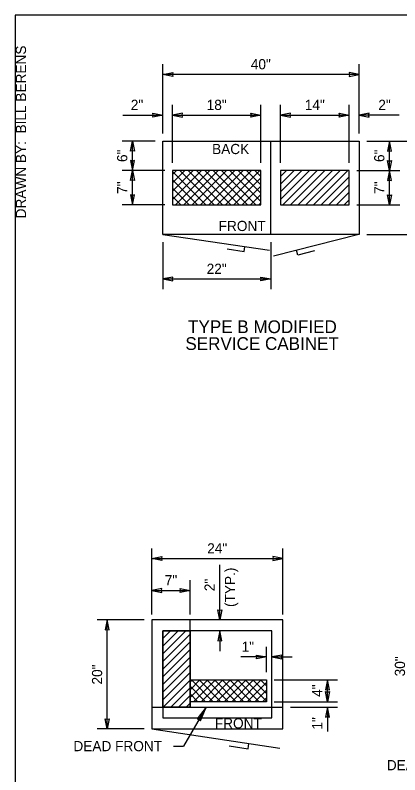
# Model space of a CAD drawing. Extents: x 99862 to 103151, y 100000 to 117076.
# Drawn here: x 99862 to 100465, y 100884 to 102076 of the extents above; entities that cross this region are included whole.
import ezdxf

# ---------------------------------------------------------------- set-up
doc = ezdxf.new("R2010")
doc.units = 0
for name, color, linetype in [('Level 1', 7, 'Continuous'), ('Level 15', 7, 'Continuous'), ('Level 20', 7, 'Continuous'), ('Level 25', 7, 'Continuous'), ('Level 40', 7, 'Continuous'), ('Level 62', 7, 'Continuous'), ('Level 8', 7, 'Continuous')]:
    doc.layers.add(name, color=color, linetype=linetype)

msp = doc.modelspace()

# ---------------------------------------------------------------- linework, layer by layer
at = {"layer": 'Level 1'}
msp.add_lwpolyline([(99862, 99999.5), (103151, 99999.5), (103151, 102075.5), (99862, 102075.5)], close=True, dxfattribs=at)
at = {"layer": 'Level 15'}
for p, q in [((100093.5, 101889.9), (100093.5, 101998.6)), ((100401.3, 101889.9), (100401.3, 101998.6)), ((100401.3, 101982.6), (100093.5, 101982.6)), ((100093.5, 101889.9), (100093.5, 101934.8)), ((100108.9, 101843.7), (100108.9, 101934.8)), ((100247.4, 101843.7), (100247.4, 101934.8)), ((100278.2, 101843.7), (100278.2, 101934.8)), ((100385.9, 101843.7), (100385.9, 101934.8)), ((100401.3, 101889.9), (100401.3, 101934.8)), ((100030.6, 101918.8), (100093.5, 101918.8)), ((100108.9, 101918.8), (100247.4, 101918.8)), ((100278.2, 101918.8), (100385.9, 101918.8)), ((100464.2, 101918.8), (100401.3, 101918.8)), ((100081.5, 101877.9), (100029.8, 101877.9)), ((100045.8, 101831.7), (100045.8, 101877.9)), ((100413.3, 101877.9), (100515, 101877.9)), ((100449, 101831.7), (100449, 101877.9)), ((100096.9, 101831.7), (100029.8, 101831.7)), ((100045.8, 101777.9), (100045.8, 101831.7)), ((100397.9, 101831.7), (100465, 101831.7)), ((100449, 101777.9), (100449, 101831.7)), ((100096.9, 101777.9), (100029.8, 101777.9)), ((100397.9, 101777.9), (100465, 101777.9)), ((100413.3, 101731.7), (100515, 101731.7)), ((100093.5, 101719.7), (100093.5, 101645.7)), ((100262.8, 101719.7), (100262.8, 101645.7)), ((100093.5, 101661.7), (100262.8, 101661.7)), ((100076.4, 101149.9), (100076.4, 101239.2)), ((100281.6, 101135.2), (100281.6, 101239.2)), ((100076.4, 101223.2), (100281.6, 101223.2)), ((100076.4, 101135.2), (100076.4, 101213)), ((100182.9, 101127), (100182.9, 101213.6)), ((100136.2, 101135.2), (100136.2, 101189.2)), ((100076.4, 101173.2), (100136.2, 101173.2)), ((100064.4, 101127), (99990.4, 101127)), ((100006.4, 100956), (100006.4, 101127)), ((100182.9, 101109.9), (100182.9, 101077.9)), ((100255.9, 101044.9), (100255.9, 101084.9)), ((100255.9, 101068.9), (100215.8, 101068.9)), ((100264.5, 101068.9), (100296.5, 101068.9)), ((100267.9, 101032.9), (100367.7, 101032.9)), ((100351.7, 100998.7), (100351.7, 101032.9)), ((100267.9, 100998.7), (100367.7, 100998.7)), ((100161.5, 100990.2), (100126.2, 100929)), ((100293.7, 100990.2), (100367.7, 100990.2)), ((100351.7, 100990.2), (100351.7, 100951.8)), ((100064.4, 100956), (99990.4, 100956)), ((100110.2, 100929), (100126.2, 100929))]:
    msp.add_line(p, q, dxfattribs=at)
for points in [[(100093.5, 101982.6), (100109.2, 101985.7), (100108.5, 101982.6), (100109.2, 101979.5)], [(100401.3, 101982.6), (100385.6, 101985.7), (100386.3, 101982.6), (100385.6, 101979.5)], [(100093.5, 101918.8), (100077.8, 101915.8), (100078.5, 101918.8), (100077.8, 101921.9)], [(100108.9, 101918.8), (100124.6, 101915.8), (100123.9, 101918.8), (100124.6, 101921.9)], [(100247.4, 101918.8), (100231.7, 101915.8), (100232.4, 101918.8), (100231.7, 101921.9)], [(100278.2, 101918.8), (100293.9, 101915.8), (100293.2, 101918.8), (100293.9, 101921.9)], [(100385.9, 101918.8), (100370.2, 101915.8), (100370.9, 101918.8), (100370.2, 101921.9)], [(100401.3, 101918.8), (100417, 101915.8), (100416.3, 101918.8), (100417, 101921.9)], [(100045.8, 101877.9), (100048.9, 101862.2), (100045.8, 101862.9), (100042.7, 101862.2)], [(100449, 101877.9), (100445.9, 101862.2), (100449, 101862.9), (100452.1, 101862.2)], [(100045.8, 101831.7), (100048.9, 101847.5), (100045.8, 101846.7), (100042.7, 101847.5)], [(100449, 101831.7), (100445.9, 101847.5), (100449, 101846.7), (100452.1, 101847.5)], [(100045.8, 101831.7), (100048.9, 101816), (100045.8, 101816.7), (100042.7, 101816)], [(100449, 101831.7), (100445.9, 101816), (100449, 101816.7), (100452.1, 101816)], [(100045.8, 101777.9), (100048.9, 101793.6), (100045.8, 101792.9), (100042.7, 101793.6)], [(100449, 101777.9), (100445.9, 101793.6), (100449, 101792.9), (100452.1, 101793.6)], [(100093.5, 101661.7), (100109.2, 101658.6), (100108.5, 101661.7), (100109.2, 101664.8)], [(100262.8, 101661.7), (100247.1, 101658.6), (100247.8, 101661.7), (100247.1, 101664.8)], [(100076.4, 101223.2), (100092.1, 101226.3), (100091.4, 101223.2), (100092.1, 101220.2)], [(100281.6, 101223.2), (100265.9, 101226.3), (100266.6, 101223.2), (100265.9, 101220.2)], [(100076.4, 101173.2), (100092.1, 101170.2), (100091.4, 101173.2), (100092.1, 101176.3)], [(100136.2, 101173.2), (100120.5, 101170.2), (100121.2, 101173.2), (100120.5, 101176.3)], [(100182.9, 101127), (100179.9, 101142.7), (100182.9, 101142), (100186, 101142.7)], [(100006.4, 101127), (100003.3, 101111.3), (100006.4, 101112), (100009.5, 101111.3)], [(100182.9, 101109.9), (100179.9, 101094.2), (100182.9, 101094.9), (100186, 101094.2)], [(100255.9, 101068.9), (100240.2, 101065.8), (100240.9, 101068.9), (100240.2, 101071.9)], [(100264.5, 101068.9), (100280.2, 101065.8), (100279.5, 101068.9), (100280.2, 101071.9)], [(100351.7, 101032.9), (100348.6, 101017.2), (100351.7, 101017.9), (100354.8, 101017.2)], [(100351.7, 100998.7), (100348.6, 101014.5), (100351.7, 101013.7), (100354.8, 101014.5)], [(100161.5, 100990.2), (100147.5, 100971.9), (100150.6, 100971.3), (100152.6, 100968.9)], [(100351.7, 100990.2), (100348.6, 100974.5), (100351.7, 100975.3), (100354.7, 100974.5)], [(100006.4, 100956), (100003.3, 100971.7), (100006.4, 100971), (100009.5, 100971.7)]]:
    msp.add_lwpolyline(points, close=True, dxfattribs=at)
at = {"layer": 'Level 25'}
for p, q in [((100136.2, 101032.9), (100255.9, 101032.9)), ((100255.9, 101032.9), (100255.9, 100998.7)), ((100255.9, 100998.7), (100136.2, 100998.7))]:
    msp.add_line(p, q, dxfattribs=at)
at = {"layer": 'Level 40'}
for p, q in [((100262.8, 101731.7), (100262.8, 101877.9)), ((100108.9, 101786.3), (100154.4, 101831.7)), ((100108.9, 101799.3), (100141.3, 101831.7)), ((100108.9, 101812.4), (100128.2, 101831.7)), ((100108.9, 101825.4), (100115.2, 101831.7)), ((100108.9, 101830.2), (100161.2, 101777.9)), ((100113.6, 101777.9), (100167.4, 101831.7)), ((100120.4, 101831.7), (100174.3, 101777.9)), ((100126.6, 101777.9), (100180.5, 101831.7)), ((100133.5, 101831.7), (100187.3, 101777.9)), ((100139.7, 101777.9), (100193.5, 101831.7)), ((100146.5, 101831.7), (100200.4, 101777.9)), ((100152.7, 101777.9), (100206.6, 101831.7)), ((100159.6, 101831.7), (100213.4, 101777.9)), ((100165.8, 101777.9), (100219.7, 101831.7)), ((100172.6, 101831.7), (100226.5, 101777.9)), ((100178.8, 101777.9), (100232.7, 101831.7)), ((100185.7, 101831.7), (100239.6, 101777.9)), ((100191.9, 101777.9), (100245.8, 101831.7)), ((100198.8, 101831.7), (100247.4, 101783.1)), ((100211.8, 101831.7), (100247.4, 101796.2)), ((100224.9, 101831.7), (100247.4, 101809.2)), ((100237.9, 101831.7), (100247.4, 101822.3)), ((100278.2, 101786.4), (100323.5, 101831.7)), ((100278.2, 101798.4), (100311.5, 101831.7)), ((100278.2, 101810.5), (100299.5, 101831.7)), ((100278.2, 101822.5), (100287.4, 101831.7)), ((100281.7, 101777.9), (100335.5, 101831.7)), ((100293.7, 101777.9), (100347.5, 101831.7)), ((100305.7, 101777.9), (100359.6, 101831.7)), ((100317.7, 101777.9), (100371.6, 101831.7)), ((100329.7, 101777.9), (100383.6, 101831.7)), ((100108.9, 101817.1), (100148.1, 101777.9)), ((100205, 101777.9), (100247.4, 101820.3)), ((100341.8, 101777.9), (100385.9, 101822)), ((100108.9, 101804.1), (100135.1, 101777.9)), ((100218, 101777.9), (100247.4, 101807.2)), ((100353.8, 101777.9), (100385.9, 101810)), ((100231.1, 101777.9), (100247.4, 101794.2)), ((100365.8, 101777.9), (100385.9, 101798)), ((100108.9, 101791), (100122, 101777.9)), ((100244.1, 101777.9), (100247.4, 101781.1)), ((100377.8, 101777.9), (100385.9, 101786)), ((100108.9, 101778), (100109, 101777.9)), ((100093.5, 101731.7), (100260.9, 101706.7)), ((100401.1, 101731.7), (100266.9, 101697.5)), ((100194.4, 101708.8), (100221.1, 101704.8)), ((100221.1, 101704.8), (100222.2, 101712.4)), ((100305.3, 101699.3), (100303.4, 101706.8)), ((100331.4, 101706), (100305.3, 101699.3)), ((100093.5, 101073.9), (100129.4, 101109.9)), ((100093.5, 101085.9), (100117.4, 101109.9)), ((100093.5, 101098), (100105.4, 101109.9)), ((100093.5, 101061.9), (100136.2, 101104.6)), ((100093.5, 101049.9), (100136.2, 101092.6)), ((100093.5, 101037.9), (100136.2, 101080.6)), ((100093.5, 101025.8), (100136.2, 101068.6)), ((100093.5, 101013.8), (100136.2, 101056.6)), ((100093.5, 101001.8), (100136.2, 101044.5)), ((100093.9, 100990.2), (100136.2, 101032.5)), ((100136.2, 101005.3), (100163.9, 101032.9)), ((100136.2, 101017.3), (100151.8, 101032.9)), ((100136.2, 101029.3), (100139.8, 101032.9)), ((100138.5, 101032.9), (100172.7, 100998.7)), ((100141.7, 100998.7), (100175.9, 101032.9)), ((100150.5, 101032.9), (100184.7, 100998.7)), ((100153.7, 100998.7), (100187.9, 101032.9)), ((100162.5, 101032.9), (100196.7, 100998.7)), ((100165.7, 100998.7), (100199.9, 101032.9)), ((100174.5, 101032.9), (100208.7, 100998.7)), ((100177.8, 100998.7), (100212, 101032.9)), ((100186.6, 101032.9), (100220.8, 100998.7)), ((100189.8, 100998.7), (100224, 101032.9)), ((100198.6, 101032.9), (100232.8, 100998.7)), ((100201.8, 100998.7), (100236, 101032.9)), ((100210.6, 101032.9), (100244.8, 100998.7)), ((100213.8, 100998.7), (100248, 101032.9)), ((100222.6, 101032.9), (100255.9, 100999.6)), ((100234.6, 101032.9), (100255.9, 101011.6)), ((100246.7, 101032.9), (100255.9, 101023.7)), ((100105.9, 100990.2), (100136.2, 101020.5)), ((100136.2, 101023.2), (100160.7, 100998.7)), ((100225.8, 100998.7), (100255.9, 101028.8)), ((100117.9, 100990.2), (100136.2, 101008.5)), ((100136.2, 101011.1), (100148.6, 100998.7)), ((100237.9, 100998.7), (100255.9, 101016.8)), ((100130, 100990.2), (100136.2, 100996.5)), ((100136.2, 100999.1), (100136.6, 100998.7)), ((100249.9, 100998.7), (100255.9, 101004.8))]:
    msp.add_line(p, q, dxfattribs=at)
for points in [[(100093.5, 101877.9), (100401.3, 101877.9), (100401.3, 101731.7), (100093.5, 101731.7)], [(100108.9, 101777.9), (100247.4, 101777.9), (100247.4, 101831.7), (100108.9, 101831.7)], [(100385.9, 101831.7), (100278.2, 101831.7), (100278.2, 101777.9), (100385.9, 101777.9)], [(100093.5, 101109.9), (100136.2, 101109.9), (100136.2, 100990.2), (100093.5, 100990.2)]]:
    msp.add_lwpolyline(points, close=True, dxfattribs=at)
at = {"layer": 'Level 8'}
for p, q in [((100136.2, 100990.2), (100136.2, 101127)), ((100076.4, 100990.2), (100281.6, 100990.2)), ((100076.4, 100956), (100277.1, 100925.9)), ((100197.6, 100929.2), (100227.2, 100924.8)), ((100227.2, 100924.8), (100228.5, 100933.2))]:
    msp.add_line(p, q, dxfattribs=at)
for points in [[(100076.4, 100956), (100281.6, 100956), (100281.6, 101127), (100076.4, 101127)], [(100093.5, 100973.1), (100264.5, 100973.1), (100264.5, 101109.9), (100093.5, 101109.9)]]:
    msp.add_lwpolyline(points, close=True, dxfattribs=at)

# ---------------------------------------------------------------- texts
at = {"layer": 'Level 20'}
for s, height, p in [('40"', 16, (100231.5, 101990.6)), ('2"', 16, (100043.3, 101926.8)), ('18"', 16, (100162.3, 101926.8)), ('14"', 16, (100316.2, 101926.8)), ('2"', 16, (100431.5, 101926.8)), ('BACK', 16, (100170.8, 101857.6)), ('FRONT', 16, (100181.1, 101736.9)), ('22"', 16, (100162.3, 101669.7)), ('TYPE B MODIFIED', 20, (100133.1, 101576.8)), ('SERVICE CABINET', 20, (100128.9, 101550.4)), ('24"', 16, (100163.1, 101231.2)), ('7"', 16, (100096.6, 101181.2)), ('1"', 16, (100217.1, 101076.9)), ('FRONT', 16, (100175.1, 100956.7)), ('DEAD FRONT', 16, (99953.3, 100921)), ('DEAD FRONT', 16, (100444.8, 100891.1))]:
    msp.add_text(s, height=height, dxfattribs=at).set_placement(p)
for s, p in [('6"', (100037.8, 101845.2)), ('6"', (100441, 101845.2)), ('7"', (100037.8, 101795.2)), ('7"', (100441, 101795.2)), ('(TYP.)', (100206.9, 101147.2)), ('2"', (100174.9, 101172)), ('30"', (100473.4, 101038.4)), ('20"', (99998.4, 101025.6)), ('4"', (100343.7, 101006.2)), ('1"', (100343.7, 100954.9))]:
    msp.add_text(s, height=16, rotation=90, dxfattribs=at).set_placement(p)
at = {"layer": 'Level 62'}
msp.add_text('DRAWN BY:  BILL BERENS', height=16, rotation=90, dxfattribs=at).set_placement((99879, 101756.8))

doc.saveas('drawing.dxf')
